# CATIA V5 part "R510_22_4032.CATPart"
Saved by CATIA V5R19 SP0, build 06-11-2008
Material "Steel": density 7860 kg/m3, Young's modulus 2e+11 Pa, Poisson ratio 0.266, thermal expansion 1.17e-05 1/K
Bounding box of the stored display mesh (mm): x -18.999 to 18.999, y -18.999 to 18.999, z 0 to 110
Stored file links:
  G:\Podręcznik\CD\Narzędzia\Arkusz Excel\Modele narzędzi\R510.22-4032.CATPart
  C:\Program Files\Dassault Systemes\B19\intel_a\startup\materials\Catalog.CATMaterial
  F:\OSTATNIE\DesignTable2.xls
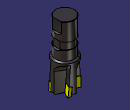
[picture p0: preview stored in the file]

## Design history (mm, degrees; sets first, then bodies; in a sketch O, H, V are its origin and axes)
Parameters
  CuttingType = "CUTTER"
  d = 32 mm {design table}
  D = 40 mm {design table}
  L = 110 mm {design table}
  l = 60 mm {design table}
  alfa = 11 deg {design table}
  gammap = 4 deg {design table}
  S = 4.76 mm {design table}
  epsilon = 85 deg {design table}
  lp = 16 mm {design table}
  x = 0.591 mm {design table}
  gammaf = -10 deg {design table}
  z = 4 {design table}
  teta = 90 deg {design table}
  `lp'` = 15.961 mm {design table}
  `lp''` = 9.4182 mm {design table}
Body1 "BODY" (main body), material "Steel"
  Sketch1 "sketch" on yz-plane, origin (0, 0, 0), H (0, 1, 0), V (0, 0, 1)
    line L1 (0, 3.0466) -> (19, 0.7137)
    line L2 (19, 0.7137) -> (19, 50)
    point P3 (19, 50)
    line L3 (19, 50) -> (19, 50)
    point P4 (16, 50)
    line L4 (16, 51.99) -> (16, 68)
    point P5 (16, 68)
    line L5 (16, 68) -> (15, 68)
    line L6 (15, 68) -> (15, 80)
    line L7 (15, 80) -> (16, 80)
    point P8 (16, 80)
    line L8 (16, 80) -> (16, 109.2929)
    line L9 (16, 109.2929) -> (15.2929, 110)
    line L10 (15.2929, 110) -> (0, 110)
    point P11 (0, 110)
    line L11 (0, 110) -> (0, 3.0466)
    construction line L12 (0, -29.1199) -> (0, 199.3445)
    point P12 (0, -29.1199)
    construction line L13 (0, 0.591) -> (20, 0.591)
    point P14 (0, 0.591)
    point P15 (20, 0.591)
    construction line L14 (0, 3.0466) -> (20, 0.591)
    axis line L15 (20, 0.591) -> (20, -5.0846)
    line L16 (19, 50) -> (16, 51.99)
    point P17 (19, 50)
    length L6 = 12 {= 0.2*l}
    distance P3 H = 50 {= L-l}
    length L9 = 1
    angle L8 L9 = 45
    distance L6 L8 = 1
    distance L8 L11 = 16 {= d/2}
    length L13 = 20 {= D/2}
    distance H L13 = 0.591 {= x}
    distance L10 L7 = 30 {= 0.5*l}
    distance P15 L2 = 1
    distance P4 P5 = 18 {= 0.3*l}
    length L16 = 3.6 {= 0.2*(0.3*l)}
    angle L1 L2 = 83
    vertical: L2 V, L4 V, L6 V, L8 V, L11 V, L12 V, L15 V
    horizontal: L3 H, L5 H, L7 H, L10 H, L13 H
    coincidence: P8 L4, P11 V, P12 V, L1 L14, P14 L12, L3 P4, L4 P4, P3 P17
  Shaft1: profile Sketch1, axis Z axis, angle 360
  Fillet1: radius 2 {= 0.1*D/2}, on edge [face of Shaft1 from Sketch1.L1 | face of Shaft1 from Sketch1.L2]
  Sketch2 on zx-plane, origin (0, 0, 0), H (-1, 0, 0), V (0, 0, 1)
    line L1 (-14, 110) -> (-14, 92)
    line L2 (-14, 92) -> (-16, 90)
    line L3 (-16, 90) -> (-16, 82)
    line L4 (-16, 82) -> (-14, 80)
    point P5 (-14, 80)
    line L5 (-14, 80) -> (-14, 68)
    line L6 (-14, 68) -> (-16, 66)
    point P7 (-16, 66)
    line L7 (-16, 66) -> (-16, 66)
    line L8 (-16, 66) -> (-19, 66)
    line L9 (-19, 66) -> (-19, 110)
    line L10 (-19, 110) -> (-14, 110)
    reference projected line E1 through (0, 0) direction (0, 1) from axis of face of Shaft1 from Sketch1.L8
    reference projected line E2 (-9.2929, 110) -> (9.2929, 110) from edge [face of Shaft1 from Sketch1.L9 | face of Shaft1 from Sketch1.L10]
    distance L3 E1 = 16 {= d/2}
    distance L1 L3 = 2
    angle L2 L3 = 45
    angle L4 L3 = 45
    length L5 = 12 {= l*0.2}
    length L1 = 18 {= 0.3*l}
    distance P5 L10 = 30 {= 0.5*l}
    distance L9 L1 = 5
    distance L7 L5 = 2
    angle L5 L6 = 45
    vertical: L1 V, L3 V, L5 V, L7 V, L9 V
    horizontal: L8 H, L10 H
    coincidence: L10 E2, L1 L5, P7 L8
  Pocket1: profile Sketch2, direction (0, -1, 0), length 8, mirrored extent
  Plane1: type Angle, Angle 150, Direction Z axis, RefPlane yz-plane
  Plane2: type Offset, Offset 1, RefPlane Plane1, reversed
  Sketch3 "gammap_os_obrotu" on Plane2, origin (0.866, -0.5, 0), H (-0.5, -0.866, 0), V (0, 0, 1)
    line L1 (1.3076, 0) -> (-0.9434, 0)
    reference intersected line E1 through (0, 0) direction (-1, 0) from xy-plane
    horizontal: L1 H
    coincidence: E1 L1
  Plane3 "gammap": type Angle, Angle -4 {= -gammap}, Direction Sketch3, RefPlane Plane2
  Plane4: type Offset, Offset 0.5, RefPlane Plane3, reversed
  Sketch4 on Plane4, origin (1.2859, -0.7424, 0.2345), H (-0.5, -0.866, 0), V (-0.0604, 0.0349, 0.9976)
    line L1 (-20, -2.3223) -> (-20, 6.2448)
    distance V L1 = 20 {= D/2}
  Plane5 "gammaf": type Angle, Angle 10 {= -gammaf}, Direction Sketch4, RefPlane Plane4
  Plane6: type Offset, Offset 0.5, RefPlane Plane5
  Plane7: type Angle, Angle 90, Direction Sketch4, RefPlane Plane5
  Sketch5 on Plane7, origin (6.1561, 18.4373, -0.5649), H (0.9396, -0.3424, 0.0007), V (0.0035, 0.0116, 0.9999)
    point P1 (5.4728, 0.561)
    line L1 (5.4728, 0.561) -> (0.661, 1.1605)
    line L2 (0.661, 1.1605) -> (-0.3008, 15.2773)
    line L3 (-0.3008, 15.2773) -> (4.3853, 16.524)
    line L4 (4.3853, 16.524) -> (5.4728, 0.561)
    reference projected line E1 (5.6139, -1.5097) -> (5.0316, 7.0376) from Sketch4
    construction line L5 (4.3853, 16.524) -> (-0.5643, 16.1867)
    axis line L6 (5.4728, 0.561) -> (1.7473, 0.3071)
    reference intersected line E2 through (0, 0.565) direction (-1, 0.0007) from xy-plane
    distance L2 L4 = 4.76 {= S}
    length L4 = 16 {= lp}
    angle L5 L3 = 11 {= alfa}
    angle L6 L1 = 11 {= alfa}
    coincidence: L4 E1, P1 E2
    perpendicularity: L5 L2
    parallelism: L6 L5
  Plane8: type Offset, Offset 20 {= D/2}, RefPlane Plane1, reversed
  Sketch6 on Plane8, origin (17.3205, -10, 0), H (-0.5, -0.866, 0), V (0, 0, 1)
    line L1 (-9.6396, -3) -> (-9.6396, 35.1125)
    arc A1 centre (-21.6396, 35.1125) radius 12 from (-9.6396, 35.1125) to (-20, 47) ccw
    point P4 (-20, 47)
    line L2 (-20, 47) -> (-20, -3)
    point P5 (-20, -3)
    line L3 (-20, -3) -> (-9.6396, -3)
    axis line L4 (-20, -3) -> (-9.6396, -2.0936)
    point P6 (-20, -3)
    point P7 (-9.6396, -2.0936)
    reference projected line E1 (-9, 50) -> (9, 50) from edge [face of Shaft1 from Sketch1.L2 | face of Shaft1 from Sketch1.L16]
    distance L2 V = 20 {= D/2}
    angle L4 L2 = 85 {= epsilon}
    distance E1 P4 = 3
    radius A1 = 12
    distance H L3 = 3
    length L4 = 10.4 {= 0.65*lp}
    vertical: L1 V, L2 V
    horizontal: L3 H
    tangency: L1 A1
    coincidence: P6 P5, P7 L1
  Pocket2: profile Sketch6, direction (-0.866, 0.5, 0), up to Plane6
  CircPattern1: of Pocket2, instances 4 {= z}, angular step 90 {= teta}, axis from Z axis
  Sketch7 on Plane5, origin (4.6728, -1.5116, 0.7463), H (-0.3414, -0.9399, -0.0041), V (-0.066, 0.0196, 0.9976)
    line L1 (-19.5145, 15.1706) -> (-9.9659, 16.1626)
    point P1 (-19.5145, 15.1706)
    reference projected point E1 (-19.5145, 15.1706) from vertex [element of Sketch5 | element of Sketch5]
    reference projected line E2 (-19.2496, -1.1279) -> (-19.4121, 8.8708) from Sketch5.L4
    length L1 = 9.6 {= 0.6*lp}
    angle E2 L1 = 85 {= epsilon}
    coincidence: P1 E1
  Slot1: profile Sketch5, centre curve Sketch7
  CircPattern2: of Slot1, instances 4 {= z}, angular step 90 {= teta}, axis from Z axis
Body2 "INSERTS"
  Sketch8 "CUT" on yz-plane, origin (0, 0, 0), H (0, 1, 0), V (0, 0, 1)
    line L1 (10.6177, 0.8208) -> (20, 0)
    point P2 (20, 0)
    line L2 (20, 0) -> (20, 15.961)
    line L3 (20, 15.961) -> (10.6177, 16.7819)
    line L4 (10.6177, 16.7819) -> (10.6177, 0.8208)
    angle L3 L4 = 85
    length L2 = 15.961 {= `lp'`}
    length L1 = 9.4182 {= `lp''`}
    distance L2 V = 20 {= D/2}
    vertical: L2 V, L4 V
    parallelism: L3 L1
    coincidence: P2 H
  Sketch9 "NOCUT" on yz-plane, origin (0, 0, 0), H (0, 1, 0), V (0, 0, 1)
    axis line L1 (20, 0) -> (0, 1.7498)
    point P1 (0, 1.7498)
    point P2 (20, 0)
    reference projected line E1 (4.0988, 1.3912) -> (10.076, 0.8682) from Sketch8.L1
    reference projected point E2 (20, 0) from vertex [element of Sketch8 | element of Sketch8]
    line L2 (0, 1.7498) -> (10.6177, 0.8208)
    point P3 (10.6177, 0.8208)
    line L3 (10.6177, 0.8208) -> (10.6177, 16.7819)
    line L4 (10.6177, 16.7819) -> (19, 16.0485)
    line L5 (19, 16.0485) -> (19, 50)
    line L6 (19, 50) -> (16, 50)
    line L7 (16, 50) -> (16, 68)
    line L8 (16, 68) -> (15, 68)
    line L9 (15, 68) -> (15, 80)
    line L10 (15, 80) -> (16, 80)
    point P11 (16, 80)
    line L11 (16, 80) -> (16, 109.2929)
    point P12 (16, 110)
    line L12 (15.2929, 110) -> (0, 110)
    point P13 (0, 110)
    line L13 (0, 110) -> (0, 1.7498)
    line L14 (16, 109.2929) -> (15.2929, 110)
    length L9 = 12 {= 0.2*l}
    length L7 = 18 {= 0.3*l}
    distance L6 H = 50 {= L-l}
    distance L11 L13 = 16 {= d/2}
    distance L9 L11 = 1
    distance P3 P2 = 9.4182 {= `lp''`}
    distance L9 L7 = 1
    distance L5 P2 = 1
    length L3 = 15.961 {= `lp'`}
    angle L10 L9 = 90
    distance P11 P12 = 30 {= 0.5*l}
    angle L11 L14 = 45
    length L14 = 1
    coincidence: P1 V, L1 E1, P2 E2, P13 V, L11 P12, L12 P12
    parallelism: L2 L1, L4 L1
    vertical: L3 V, L5 V, L7 V, L9 V, L11 V, L13 V
    horizontal: L6 H, L8 H, L12 H
  Sketch10 on Plane7, origin (6.1561, 18.4373, -0.5649), H (0.9396, -0.3424, 0.0007), V (0.0035, 0.0116, 0.9999)
    point P1 (5.4728, 0.561)
    line L1 (5.4728, 0.561) -> (0.661, 1.1605)
    line L2 (0.661, 1.1605) -> (-0.3008, 15.2773)
    line L3 (-0.3008, 15.2773) -> (4.3853, 16.524)
    line L4 (4.3853, 16.524) -> (5.4728, 0.561)
    reference intersected line E1 through (5.4561, 0.8073) direction (0.068, -0.9977) from Plane5
    reference intersected line E2 through (0, 0.565) direction (-1, 0.0007) from xy-plane
    construction line L5 (4.3853, 16.524) -> (-6.5695, 15.7776)
    axis line L6 (5.4728, 0.561) -> (-1.2013, 0.1063)
    distance L2 L4 = 4.76 {= S}
    length L4 = 16 {= lp}
    angle L3 L5 = 11 {= alfa}
    angle L6 L1 = 11 {= alfa}
    coincidence: L4 E1, E2 P1
    perpendicularity: L5 L2
    parallelism: L6 L5
  Sketch11 on Plane5, origin (4.6728, -1.5116, 0.7463), H (-0.3414, -0.9399, -0.0041), V (-0.066, 0.0196, 0.9976)
    line L1 (-19.5145, 15.1706) -> (-9.9659, 16.1626)
    point P1 (-19.5145, 15.1706)
    reference projected point E1 (-19.5145, 15.1706) from vertex [element of Sketch10 | element of Sketch10]
    reference projected line E2 (-19.2546, -0.816) -> (-19.4172, 9.1826) from Sketch10.L4
    angle L1 E2 = 85 {= epsilon}
    length L1 = 9.6 {= 0.6*lp}
    coincidence: P1 E1
  Rib1: profile Sketch10, centre curve Sketch11
  CircPattern3: of the body so far, instances 4 {= z}, angular step 90 {= teta}, axis from Z axis
  Sketch12 on face of Rib1, origin (0.2242, 0.2239, 2.4875), H (0.7983, -0.5955, -0.09), V (-0.5837, -0.8018, 0.1281)
    point P1 (-0.6694, -19.8899)
    line L1 (-0.6694, -19.8899) -> (-5.0602, -17.5917)
    line L2 (-5.0602, -17.5917) -> (-5.3158, -18.5023)
    point P3 (-5.3158, -18.5023)
    line L3 (-5.3158, -18.5023) -> (-0.6694, -19.8899)
    reference projected point E1 (-0.6694, -19.8899) from vertex [face of Rib1 | face of Rib1 | face of Rib1]
    reference projected line E2 (-5.5799, -18.4235) -> (-2.4758, -19.3504) from edge [face of Rib1 | face of Rib1]
    reference projected point E3 (-5.3158, -18.5023) from vertex [face of Rib1 | face of Rib1 | face of Rib1]
    reference projected line E4 (-2.6566, -9.0259) -> (-1.0355, -3.249) from edge [face of Rib1 | face of Rib1]
    angle L1 L3 = 11
    coincidence: E1 P1, L3 E2, P3 E3, L2 E4
  Pocket3: profile Sketch12, direction along edge [face of Rib1 | face of Rib1], length 16 {= lp}
  CircPattern4: of Pocket3, instances 4 {= z}, angular step 90 {= teta}, axis from Z axis
Relations
  design table, configuration 7, drives d, D, L, l, alfa, gammap, S, epsilon, lp, x, gammaf, z, teta, `lp'`, `lp''`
